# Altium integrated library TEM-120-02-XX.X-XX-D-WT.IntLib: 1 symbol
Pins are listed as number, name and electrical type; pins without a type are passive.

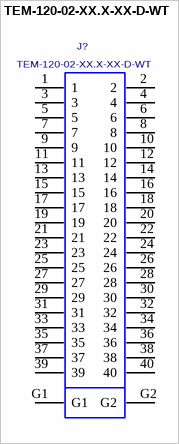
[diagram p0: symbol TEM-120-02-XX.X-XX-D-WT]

## TEM-120-02-XX.X-XX-D-WT
designator J?
0.8MM TIGER EYE MICRO TERMINAL, WELD TABS, 40PINS.; MANUFACTURER: SAMTEC
footprint TEM-120-02-XX.X-XX-D-WT
pins: 1, 2, 3, 4, 5, 6, 7, 8, 9, 10, 11, 12, 13, 14, 15, 16, 17, 18, 19, 20, 21, 22, 23, 24, 25, 26, 27, 28, 29, 30, 31, 32, 33, 34, 35, 36, 37, 38, 39, 40, G1, G2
